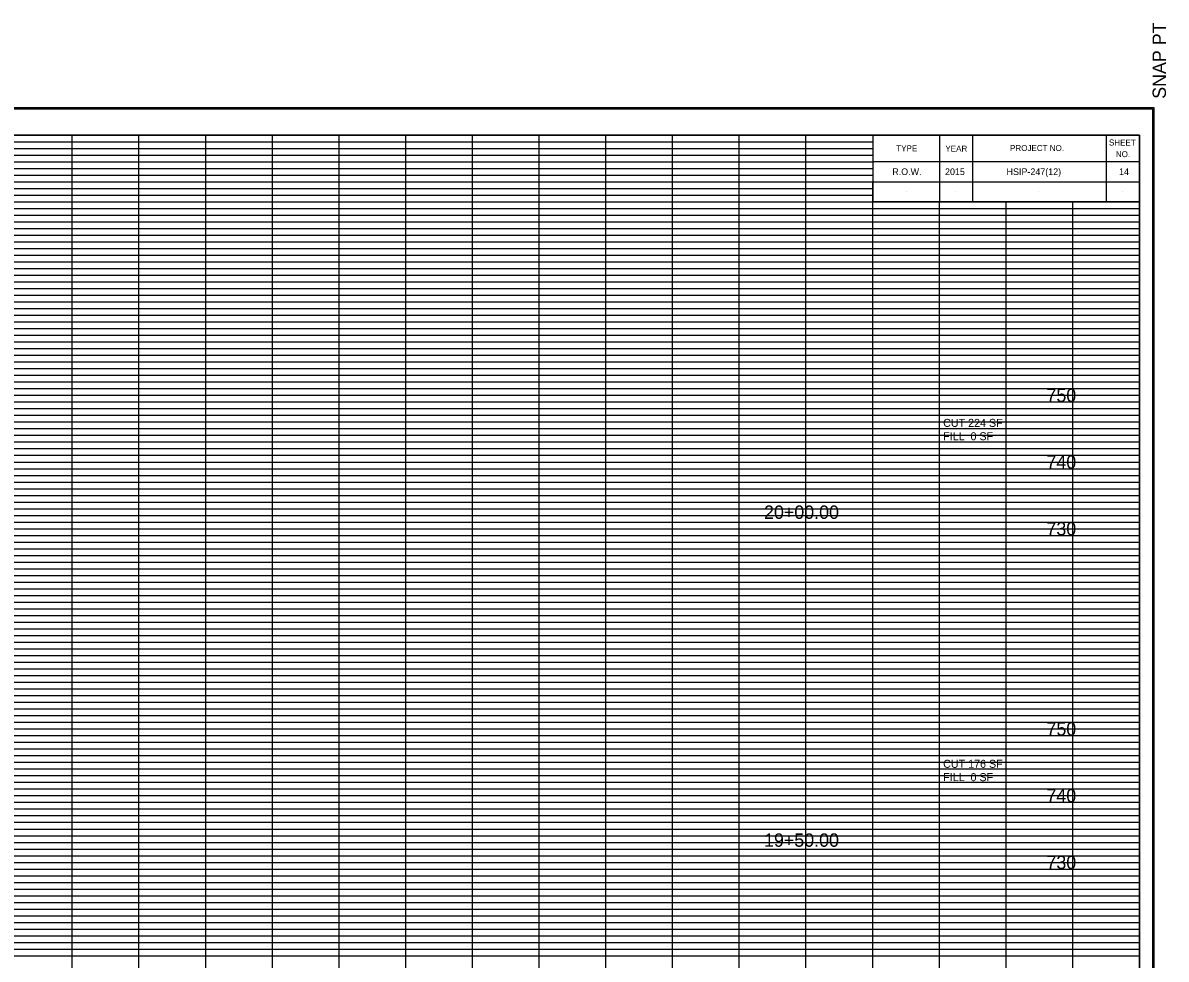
# Model space of a CAD drawing. Extents: x -200 to 1704, y -325 to 2307.
# Drawn here: x 1152.6 to 1324, y 2166.5 to 2306.8 of the extents above; entities that cross this region are included whole.
import ezdxf

# ---------------------------------------------------------------- set-up
doc = ezdxf.new("R2010")
doc.units = 0
for name, color, linetype in [('DESIGN - SCRATCH - User 1', 7, 'Continuous'), ('DESIGN - SHEET - Corner Text', 7, 'Continuous'), ('DESIGN - SHEET - Light Grid', 7, 'Continuous'), ('DESIGN - SHEET - Linework', 7, 'Continuous'), ('DESIGN - SHEET - Plot Shape', 7, 'Continuous'), ('DESIGN - TYPICAL - Text', 7, 'Continuous')]:
    doc.layers.add(name, color=color, linetype=linetype)

msp = doc.modelspace()

# ---------------------------------------------------------------- linework, layer by layer
at = {"layer": 'DESIGN - SCRATCH - User 1'}
for p, q in [((1285, 2284.5), (1285, 2284.5)), ((1292.4, 2284.5), (1292.4, 2284.5)), ((1304.9, 2284.5), (1304.9, 2284.5)), ((1317.4, 2284.5), (1317.4, 2284.5)), ((1285, 2281.5), (1285, 2281.5)), ((1292.4, 2281.5), (1292.4, 2281.5)), ((1304.9, 2281.5), (1304.9, 2281.5)), ((1317.4, 2281.5), (1317.4, 2281.5))]:
    msp.add_line(p, q, dxfattribs=at)
at = {"layer": 'DESIGN - SHEET - Light Grid'}
for p, q in [((1080, 2289), (1160, 2289)), ((1160, 2289), (1240, 2289)), ((1240, 2289), (1280, 2289)), ((1080, 2288), (1160, 2288)), ((1080, 2287), (1160, 2287)), ((1160, 2288), (1240, 2288)), ((1160, 2287), (1240, 2287)), ((1240, 2288), (1280, 2288)), ((1240, 2287), (1280, 2287)), ((1080, 2286), (1160, 2286)), ((1080, 2285), (1160, 2285)), ((1160, 2286), (1240, 2286)), ((1160, 2285), (1240, 2285)), ((1240, 2286), (1280, 2286)), ((1240, 2285), (1280, 2285)), ((1080, 2284), (1160, 2284)), ((1160, 2284), (1240, 2284)), ((1240, 2284), (1280, 2284)), ((1080, 2283), (1160, 2283)), ((1080, 2282), (1160, 2282)), ((1160, 2283), (1240, 2283)), ((1160, 2282), (1240, 2282)), ((1240, 2283), (1280, 2283)), ((1240, 2282), (1280, 2282)), ((1080, 2281), (1160, 2281)), ((1160, 2281), (1240, 2281)), ((1240, 2281), (1280, 2281)), ((1080, 2279), (1160, 2279)), ((1160, 2279), (1240, 2279)), ((1240, 2279), (1320, 2279)), ((1080, 2278), (1160, 2278)), ((1080, 2277), (1160, 2277)), ((1160, 2278), (1240, 2278)), ((1160, 2277), (1240, 2277)), ((1240, 2278), (1320, 2278)), ((1240, 2277), (1320, 2277)), ((1080, 2276), (1160, 2276)), ((1080, 2275), (1160, 2275)), ((1160, 2276), (1240, 2276)), ((1160, 2275), (1240, 2275)), ((1240, 2276), (1320, 2276)), ((1240, 2275), (1320, 2275)), ((1080, 2274), (1160, 2274)), ((1080, 2273), (1160, 2273)), ((1160, 2274), (1240, 2274)), ((1160, 2273), (1240, 2273)), ((1240, 2274), (1320, 2274)), ((1240, 2273), (1320, 2273)), ((1080, 2272), (1160, 2272)), ((1160, 2272), (1240, 2272)), ((1240, 2272), (1320, 2272)), ((1080, 2271), (1160, 2271)), ((1160, 2271), (1240, 2271)), ((1240, 2271), (1320, 2271)), ((1080, 2269), (1160, 2269)), ((1080, 2268), (1160, 2268)), ((1160, 2269), (1240, 2269)), ((1160, 2268), (1240, 2268)), ((1240, 2269), (1320, 2269)), ((1240, 2268), (1320, 2268)), ((1080, 2267), (1160, 2267)), ((1160, 2267), (1240, 2267)), ((1240, 2267), (1320, 2267)), ((1080, 2266), (1160, 2266)), ((1080, 2265), (1160, 2265)), ((1160, 2266), (1240, 2266)), ((1160, 2265), (1240, 2265)), ((1240, 2266), (1320, 2266)), ((1240, 2265), (1320, 2265)), ((1080, 2264), (1160, 2264)), ((1080, 2263), (1160, 2263)), ((1160, 2264), (1240, 2264)), ((1160, 2263), (1240, 2263)), ((1240, 2264), (1320, 2264)), ((1240, 2263), (1320, 2263)), ((1080, 2262), (1160, 2262)), ((1080, 2261), (1160, 2261)), ((1160, 2262), (1240, 2262)), ((1160, 2261), (1240, 2261)), ((1240, 2262), (1320, 2262)), ((1240, 2261), (1320, 2261)), ((1080, 2259), (1160, 2259)), ((1080, 2258), (1160, 2258)), ((1160, 2259), (1240, 2259)), ((1160, 2258), (1240, 2258)), ((1240, 2259), (1320, 2259)), ((1240, 2258), (1320, 2258)), ((1080, 2257), (1160, 2257)), ((1080, 2256), (1160, 2256)), ((1160, 2257), (1240, 2257)), ((1160, 2256), (1240, 2256)), ((1240, 2257), (1320, 2257)), ((1240, 2256), (1320, 2256)), ((1080, 2255), (1160, 2255)), ((1160, 2255), (1240, 2255)), ((1240, 2255), (1320, 2255)), ((1080, 2254), (1160, 2254)), ((1080, 2253), (1160, 2253)), ((1160, 2254), (1240, 2254)), ((1160, 2253), (1240, 2253)), ((1240, 2254), (1320, 2254)), ((1240, 2253), (1320, 2253)), ((1080, 2252), (1160, 2252)), ((1080, 2251), (1160, 2251)), ((1160, 2252), (1240, 2252)), ((1160, 2251), (1240, 2251)), ((1240, 2252), (1320, 2252)), ((1240, 2251), (1320, 2251)), ((1080, 2249), (1160, 2249)), ((1160, 2249), (1240, 2249)), ((1240, 2249), (1320, 2249)), ((1080, 2248), (1160, 2248)), ((1160, 2248), (1240, 2248)), ((1240, 2248), (1320, 2248)), ((1080, 2247), (1160, 2247)), ((1080, 2246), (1160, 2246)), ((1160, 2247), (1240, 2247)), ((1160, 2246), (1240, 2246)), ((1240, 2247), (1320, 2247)), ((1240, 2246), (1320, 2246)), ((1080, 2245), (1160, 2245)), ((1080, 2244), (1160, 2244)), ((1160, 2245), (1240, 2245)), ((1160, 2244), (1240, 2244)), ((1240, 2245), (1320, 2245)), ((1240, 2244), (1320, 2244)), ((1080, 2243), (1160, 2243)), ((1160, 2243), (1240, 2243)), ((1240, 2243), (1320, 2243)), ((1080, 2242), (1160, 2242)), ((1080, 2241), (1160, 2241)), ((1160, 2242), (1240, 2242)), ((1160, 2241), (1240, 2241)), ((1240, 2242), (1320, 2242)), ((1240, 2241), (1320, 2241)), ((1080, 2239), (1160, 2239)), ((1160, 2239), (1240, 2239)), ((1240, 2239), (1320, 2239)), ((1080, 2238), (1160, 2238)), ((1080, 2237), (1160, 2237)), ((1160, 2238), (1240, 2238)), ((1160, 2237), (1240, 2237)), ((1240, 2238), (1320, 2238)), ((1240, 2237), (1320, 2237)), ((1080, 2236), (1160, 2236)), ((1160, 2236), (1240, 2236)), ((1240, 2236), (1320, 2236)), ((1080, 2235), (1160, 2235)), ((1080, 2234), (1160, 2234)), ((1160, 2235), (1240, 2235)), ((1160, 2234), (1240, 2234)), ((1240, 2235), (1320, 2235)), ((1240, 2234), (1320, 2234)), ((1080, 2233), (1160, 2233)), ((1080, 2232), (1160, 2232)), ((1160, 2233), (1240, 2233)), ((1160, 2232), (1240, 2232)), ((1240, 2233), (1320, 2233)), ((1240, 2232), (1320, 2232)), ((1080, 2231), (1160, 2231)), ((1160, 2231), (1240, 2231)), ((1240, 2231), (1320, 2231)), ((1080, 2229), (1160, 2229)), ((1160, 2229), (1240, 2229)), ((1240, 2229), (1320, 2229)), ((1080, 2228), (1160, 2228)), ((1080, 2227), (1160, 2227)), ((1160, 2228), (1240, 2228)), ((1160, 2227), (1240, 2227)), ((1240, 2228), (1320, 2228)), ((1240, 2227), (1320, 2227)), ((1080, 2226), (1160, 2226)), ((1080, 2225), (1160, 2225)), ((1160, 2226), (1240, 2226)), ((1160, 2225), (1240, 2225)), ((1240, 2226), (1320, 2226)), ((1240, 2225), (1320, 2225)), ((1080, 2224), (1160, 2224)), ((1160, 2224), (1240, 2224)), ((1240, 2224), (1320, 2224)), ((1080, 2223), (1160, 2223)), ((1080, 2222), (1160, 2222)), ((1160, 2223), (1240, 2223)), ((1160, 2222), (1240, 2222)), ((1240, 2223), (1320, 2223)), ((1240, 2222), (1320, 2222)), ((1080, 2221), (1160, 2221)), ((1160, 2221), (1240, 2221)), ((1240, 2221), (1320, 2221)), ((1080, 2219), (1160, 2219)), ((1160, 2219), (1240, 2219)), ((1240, 2219), (1320, 2219)), ((1080, 2218), (1160, 2218)), ((1080, 2217), (1160, 2217)), ((1160, 2218), (1240, 2218)), ((1160, 2217), (1240, 2217)), ((1240, 2218), (1320, 2218)), ((1240, 2217), (1320, 2217)), ((1080, 2216), (1160, 2216)), ((1080, 2215), (1160, 2215)), ((1160, 2216), (1240, 2216)), ((1160, 2215), (1240, 2215)), ((1240, 2216), (1320, 2216)), ((1240, 2215), (1320, 2215)), ((1080, 2214), (1160, 2214)), ((1080, 2213), (1160, 2213)), ((1160, 2214), (1240, 2214)), ((1160, 2213), (1240, 2213)), ((1240, 2214), (1320, 2214)), ((1240, 2213), (1320, 2213)), ((1080, 2212), (1160, 2212)), ((1160, 2212), (1240, 2212)), ((1240, 2212), (1320, 2212)), ((1080, 2211), (1160, 2211)), ((1160, 2211), (1240, 2211)), ((1240, 2211), (1320, 2211)), ((1080, 2209), (1160, 2209)), ((1080, 2208), (1160, 2208)), ((1160, 2209), (1240, 2209)), ((1160, 2208), (1240, 2208)), ((1240, 2209), (1320, 2209)), ((1240, 2208), (1320, 2208)), ((1080, 2207), (1160, 2207)), ((1160, 2207), (1240, 2207)), ((1240, 2207), (1320, 2207)), ((1080, 2206), (1160, 2206)), ((1080, 2205), (1160, 2205)), ((1160, 2206), (1240, 2206)), ((1160, 2205), (1240, 2205)), ((1240, 2206), (1320, 2206)), ((1240, 2205), (1320, 2205)), ((1080, 2204), (1160, 2204)), ((1080, 2203), (1160, 2203)), ((1160, 2204), (1240, 2204)), ((1160, 2203), (1240, 2203)), ((1240, 2204), (1320, 2204)), ((1240, 2203), (1320, 2203)), ((1080, 2202), (1160, 2202)), ((1080, 2201), (1160, 2201)), ((1160, 2202), (1240, 2202)), ((1160, 2201), (1240, 2201)), ((1240, 2202), (1320, 2202)), ((1240, 2201), (1320, 2201)), ((1080, 2199), (1160, 2199)), ((1080, 2198), (1160, 2198)), ((1160, 2199), (1240, 2199)), ((1160, 2198), (1240, 2198)), ((1240, 2199), (1320, 2199)), ((1240, 2198), (1320, 2198)), ((1080, 2197), (1160, 2197)), ((1080, 2196), (1160, 2196)), ((1160, 2197), (1240, 2197)), ((1160, 2196), (1240, 2196)), ((1240, 2197), (1320, 2197)), ((1240, 2196), (1320, 2196)), ((1080, 2195), (1160, 2195)), ((1160, 2195), (1240, 2195)), ((1240, 2195), (1320, 2195)), ((1080, 2194), (1160, 2194)), ((1080, 2193), (1160, 2193)), ((1160, 2194), (1240, 2194)), ((1160, 2193), (1240, 2193)), ((1240, 2194), (1320, 2194)), ((1240, 2193), (1320, 2193)), ((1080, 2192), (1160, 2192)), ((1080, 2191), (1160, 2191)), ((1160, 2192), (1240, 2192)), ((1160, 2191), (1240, 2191)), ((1240, 2192), (1320, 2192)), ((1240, 2191), (1320, 2191)), ((1080, 2189), (1160, 2189)), ((1160, 2189), (1240, 2189)), ((1240, 2189), (1320, 2189)), ((1080, 2188), (1160, 2188)), ((1160, 2188), (1240, 2188)), ((1240, 2188), (1320, 2188)), ((1080, 2187), (1160, 2187)), ((1080, 2186), (1160, 2186)), ((1160, 2187), (1240, 2187)), ((1160, 2186), (1240, 2186)), ((1240, 2187), (1320, 2187)), ((1240, 2186), (1320, 2186)), ((1080, 2185), (1160, 2185)), ((1080, 2184), (1160, 2184)), ((1160, 2185), (1240, 2185)), ((1160, 2184), (1240, 2184)), ((1240, 2185), (1320, 2185)), ((1240, 2184), (1320, 2184)), ((1080, 2183), (1160, 2183)), ((1160, 2183), (1240, 2183)), ((1240, 2183), (1320, 2183)), ((1080, 2182), (1160, 2182)), ((1080, 2181), (1160, 2181)), ((1160, 2182), (1240, 2182)), ((1160, 2181), (1240, 2181)), ((1240, 2182), (1320, 2182)), ((1240, 2181), (1320, 2181)), ((1080, 2179), (1160, 2179)), ((1160, 2179), (1240, 2179)), ((1240, 2179), (1320, 2179)), ((1080, 2178), (1160, 2178)), ((1080, 2177), (1160, 2177)), ((1160, 2178), (1240, 2178)), ((1160, 2177), (1240, 2177)), ((1240, 2178), (1320, 2178)), ((1240, 2177), (1320, 2177)), ((1080, 2176), (1160, 2176)), ((1160, 2176), (1240, 2176)), ((1240, 2176), (1320, 2176)), ((1080, 2175), (1160, 2175)), ((1080, 2174), (1160, 2174)), ((1160, 2175), (1240, 2175)), ((1160, 2174), (1240, 2174)), ((1240, 2175), (1320, 2175)), ((1240, 2174), (1320, 2174)), ((1080, 2173), (1160, 2173)), ((1080, 2172), (1160, 2172)), ((1160, 2173), (1240, 2173)), ((1160, 2172), (1240, 2172)), ((1240, 2173), (1320, 2173)), ((1240, 2172), (1320, 2172)), ((1080, 2171), (1160, 2171)), ((1160, 2171), (1240, 2171)), ((1240, 2171), (1320, 2171)), ((1080, 2169), (1160, 2169)), ((1160, 2169), (1240, 2169)), ((1240, 2169), (1320, 2169)), ((1080, 2168), (1160, 2168)), ((1080, 2167), (1160, 2167)), ((1160, 2168), (1240, 2168)), ((1160, 2167), (1240, 2167)), ((1240, 2168), (1320, 2168)), ((1240, 2167), (1320, 2167))]:
    msp.add_line(p, q, dxfattribs=at)
at = {"layer": 'DESIGN - SHEET - Linework'}
for p, q in [((981.77, 2294.14), (1322.17, 2294.14)), ((1322.17, 2294.14), (1322.17, 2075.86)), ((1160, 2080), (1160, 2290)), ((1170, 2080), (1170, 2290)), ((1180, 2080), (1180, 2290)), ((1190, 2080), (1190, 2290)), ((1200, 2080), (1200, 2290)), ((1210, 2080), (1210, 2290)), ((1220, 2080), (1220, 2290)), ((1230, 2080), (1230, 2290)), ((1240, 2080), (1240, 2290)), ((1250, 2080), (1250, 2290)), ((1260, 2080), (1260, 2290)), ((1270, 2080), (1270, 2290)), ((1000, 2280), (1280, 2280)), ((1280, 2080), (1280, 2280)), ((1290, 2080), (1290, 2280)), ((1300, 2080), (1300, 2280)), ((1310, 2080), (1310, 2280)), ((1000, 2270), (1320, 2270)), ((1000, 2260), (1320, 2260)), ((1000, 2250), (1320, 2250)), ((1000, 2240), (1320, 2240)), ((1000, 2230), (1320, 2230)), ((1000, 2220), (1320, 2220)), ((1000, 2210), (1320, 2210)), ((1000, 2200), (1320, 2200)), ((1000, 2190), (1320, 2190)), ((1000, 2180), (1320, 2180)), ((1000, 2170), (1320, 2170))]:
    msp.add_line(p, q, dxfattribs=at)
for points in [[(1000, 2290), (1000, 2080), (1320, 2080), (1320, 2290), (1000, 2290)], [(1280, 2290), (1280, 2280), (1320, 2280), (1320, 2290), (1315, 2290), (1315, 2280), (1295, 2280), (1295, 2290), (1290, 2290), (1290, 2280), (1320, 2280), (1280, 2280), (1280, 2283), (1320, 2283), (1320, 2286), (1280, 2286)]]:
    msp.add_lwpolyline(points, dxfattribs=at)
at = {"layer": 'DESIGN - SHEET - Plot Shape'}
for points in [[(981.97, 2293.94), (1321.97, 2293.94), (1321.97, 2076.06), (981.97, 2076.06)], [(991.5, 2290), (1320, 2290), (1320, 2077.5), (991.5, 2077.5)]]:
    msp.add_lwpolyline(points, close=True, dxfattribs=at)

# ---------------------------------------------------------------- texts
at = {"layer": 'DESIGN - SHEET - Corner Text'}
msp.add_text('  SNAP PT', height=2, rotation=90, dxfattribs=at).set_placement((1323.97, 2293.94))
for s, height, p in [('TYPE', 0.9, (1283.54, 2287.56)), ('YEAR', 0.9, (1290.9, 2287.52)), ('PROJECT NO.', 0.9, (1300.6, 2287.6)), ('SHEET', 0.9, (1315.43, 2288.43)), ('NO.', 0.9, (1316.46, 2286.69)), ('R.O.W.', 1, (1282.94, 2284)), ('2015', 1, (1290.85, 2284)), ('HSIP-247(12)', 1, (1300.08, 2284)), ('14', 1, (1316.94, 2284))]:
    msp.add_text(s, height=height, dxfattribs=at).set_placement(p)
at = {"layer": 'DESIGN - TYPICAL - Text'}
for s, height, p in [('     750     ', 2, (1302.34, 2250)), ('CUT 224 SF', 1.2, (1290.57, 2246.26)), ('FILL  0 SF', 1.2, (1290.57, 2244.26)), ('     740     ', 2, (1302.34, 2240)), ('     20+00.00     ', 2, (1260, 2232.48)), ('     730     ', 2, (1302.34, 2230)), ('     750     ', 2, (1302.34, 2200)), ('CUT 176 SF', 1.2, (1290.57, 2195.17)), ('FILL  0 SF', 1.2, (1290.57, 2193.17)), ('     740     ', 2, (1302.34, 2190)), ('     19+50.00     ', 2, (1260, 2183.34)), ('     730     ', 2, (1302.34, 2180))]:
    msp.add_text(s, height=height, dxfattribs=at).set_placement(p)

doc.saveas('drawing.dxf')
